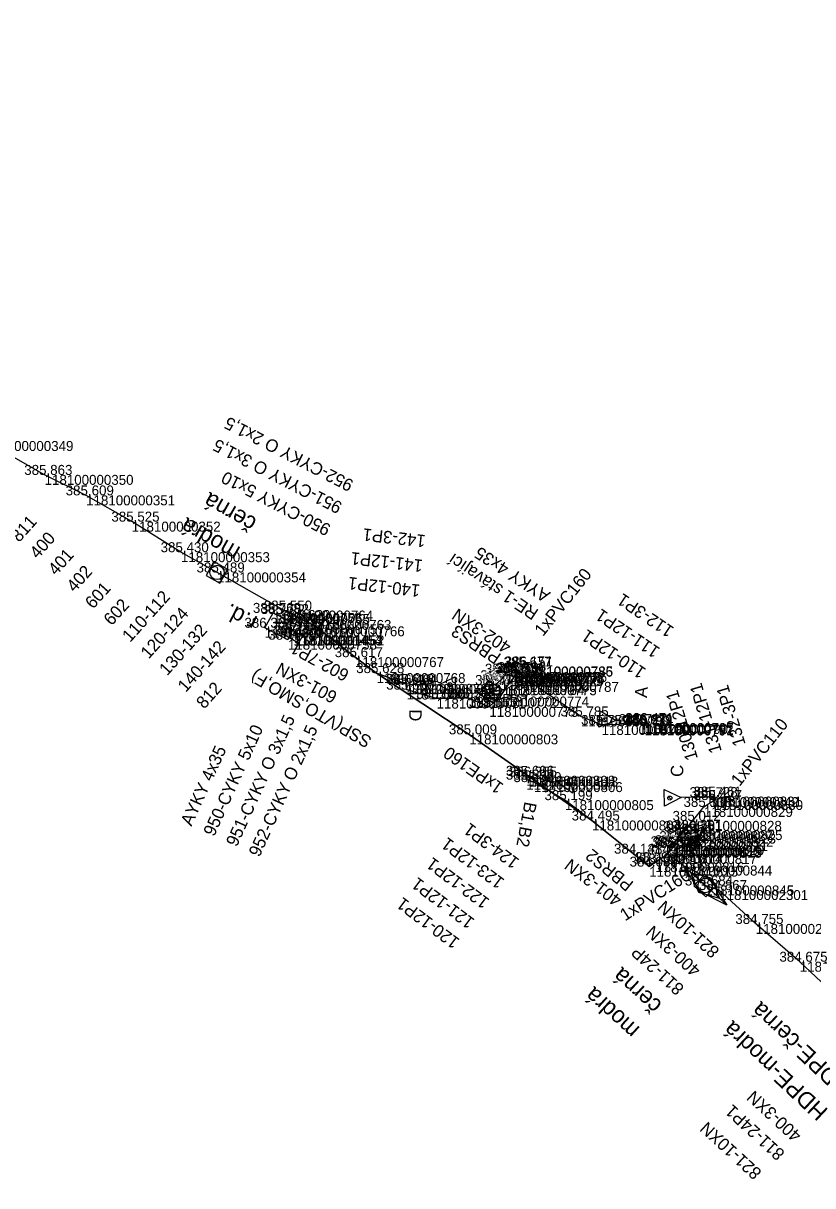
# Model space of a CAD drawing. Extents: x -724084 to -720954, y -948423 to -945131.
# Drawn here: x -721591.6 to -721496.5, y -947941.8 to -947801.8 of the extents above; entities that cross this region are included whole.
import ezdxf

# ---------------------------------------------------------------- set-up
doc = ezdxf.new("R2010")
doc.units = 0
for name, color, linetype in [('Vrstva 25', 7, 'Continuous'), ('Vrstva 26', 7, 'Continuous'), ('Vrstva 27', 7, 'Continuous'), ('Vrstva 28', 7, 'Continuous'), ('Vrstva 3', 7, 'Continuous'), ('Vrstva 31', 7, 'Continuous'), ('Vrstva 33', 7, 'Continuous'), ('Vrstva 35', 7, 'Continuous'), ('Vrstva 4', 7, 'Continuous'), ('Vrstva 60', 7, 'Continuous'), ('Vrstva 61', 7, 'Continuous')]:
    doc.layers.add(name, color=color, linetype=linetype)

msp = doc.modelspace()

# ---------------------------------------------------------------- linework, layer by layer
at = {"layer": 'Vrstva 25'}
for points in [[(-721557.94, -947875.57), (-721558.44, -947876.44), (-721560.17, -947875.43), (-721559.67, -947874.57), (-721557.94, -947875.57)], [(-721530.42, -947879.79), (-721530.98, -947880.62), (-721532.64, -947879.51), (-721532.08, -947878.68), (-721530.42, -947879.79)]]:
    msp.add_lwpolyline(points, dxfattribs=at)
at = {"layer": 'Vrstva 26'}
for points in [[(-721557.95, -947873.64), (-721560.15, -947872.51), (-721560.53, -947872.92)], [(-721559.05, -947875.5), (-721558.98, -947875.53), (-721558.79, -947875.5), (-721557.95, -947873.64)], [(-721531.25, -947879.24), (-721531.28, -947879.28), (-721531.98, -947879.92), (-721533.23, -947881.51), (-721534.14, -947882.86), (-721535.45, -947884.11), (-721538, -947883.03), (-721541.8, -947883.11), (-721545.42, -947882.03), (-721545.45, -947881.34), (-721549.03, -947880.04), (-721551.62, -947878.12), (-721556.35, -947874.41), (-721557.95, -947873.64)]]:
    msp.add_lwpolyline(points, dxfattribs=at)
at = {"layer": 'Vrstva 27'}
for p, q in [((-721532.25, -947880.11), (-721532.33, -947880.06)), ((-721513.24, -947901.02), (-721513.32, -947900.96))]:
    msp.add_line(p, q, dxfattribs=at)
for points in [[(-721559.7, -947876.02), (-721562.49, -947874.58), (-721561.47, -947872.79), (-721558.78, -947874.16), (-721559.7, -947876.02)], [(-721532.29, -947880.08), (-721532.46, -947880.37), (-721532.77, -947880.42), (-721533.52, -947880.12), (-721534.07, -947880.9), (-721534.72, -947881.47)], [(-721513.28, -947900.99), (-721513.06, -947900.77), (-721512.62, -947900.28), (-721511.95, -947899.76), (-721511.64, -947899.37), (-721510.86, -947898.95)]]:
    msp.add_lwpolyline(points, dxfattribs=at)
for centre in [(-721532.29, -947880.08), (-721513.28, -947900.99)]:
    msp.add_circle(centre, 0.5, dxfattribs=at)
at = {"layer": 'Vrstva 28'}
for p, q in [((-721506.87, -947907.96), (-721512.03, -947903.27)), ((-721510.23, -947906.48), (-721511.17, -947904.05)), ((-721511.17, -947904.05), (-721508.67, -947904.75)), ((-721508.67, -947904.75), (-721507.73, -947907.18)), ((-721507.73, -947907.18), (-721510.23, -947906.48))]:
    msp.add_line(p, q, dxfattribs=at)
for points in [[(-721560.15, -947872.51), (-721568.24, -947867.92), (-721572.58, -947865.48), (-721578.51, -947861.8), (-721584, -947858.64), (-721589, -947856.17), (-721596.24, -947852.09), (-721602.86, -947848.59), (-721606.08, -947846.62), (-721610.38, -947844.41), (-721614.4, -947841.85), (-721618.55, -947839.33), (-721627.06, -947834.09), (-721634.1, -947829.95), (-721642.58, -947825.32), (-721647.14, -947823.7), (-721653.32, -947819.98), (-721655.37, -947818.3), (-721658.37, -947816.2), (-721665.02, -947812.16), (-721667.86, -947809.89), (-721672.1, -947807.72), (-721674.53, -947807.12), (-721683.46, -947801.78)], [(-721560.53, -947872.92), (-721560.15, -947872.51)], [(-721560.15, -947872.51), (-721557.95, -947873.64)], [(-721559.05, -947875.5), (-721558.98, -947875.53), (-721558.79, -947875.5), (-721557.95, -947873.64)], [(-721557.95, -947873.64), (-721556.35, -947874.41), (-721551.62, -947878.12), (-721549.03, -947880.04)], [(-721549.03, -947880.04), (-721537.87, -947887.42), (-721523.09, -947897.79)], [(-721549.03, -947880.04), (-721545.45, -947881.34)], [(-721545.45, -947881.34), (-721545.42, -947882.03), (-721541.8, -947883.11), (-721538, -947883.03), (-721535.45, -947884.11), (-721534.14, -947882.86), (-721533.23, -947881.51), (-721531.98, -947879.92)], [(-721531.98, -947879.92), (-721532.21, -947879.99), (-721532.29, -947880.08)], [(-721516.72, -947886.05), (-721516.74, -947886.22), (-721516.75, -947886.35), (-721517.42, -947886.18), (-721521.94, -947886.29), (-721524.42, -947885.26), (-721530.56, -947881.1), (-721531.98, -947879.92)], [(-721545.05, -947881.39), (-721545.45, -947881.34)], [(-721523.09, -947897.79), (-721526.36, -947895.34), (-721530.09, -947893.17), (-721531, -947892.87), (-721531.01, -947892.41), (-721530.64, -947892.51)], [(-721513.94, -947901.83), (-721513.57, -947900.89), (-721512.03, -947899.08), (-721510.94, -947897.84), (-721509.61, -947896.16), (-721508.39, -947895.33), (-721508.52, -947894.91), (-721508.88, -947894.98)], [(-721523.09, -947897.79), (-721518.09, -947901.79), (-721516.2, -947903.35), (-721515.45, -947902.81), (-721513.94, -947901.83)], [(-721513.94, -947901.83), (-721513.36, -947901.08), (-721513.28, -947900.99)], [(-721448.03, -947967.83), (-721449.45, -947966.46), (-721453.79, -947960.88), (-721457.95, -947955.95), (-721463.02, -947949.85), (-721466.62, -947945.71), (-721471.84, -947940.17), (-721476.02, -947936), (-721481.4, -947930.25), (-721486.36, -947925.65), (-721492.33, -947920.18), (-721498.07, -947914.8), (-721503.37, -947910.25), (-721507.77, -947906.17), (-721509.45, -947905.62), (-721512.09, -947903.22), (-721513.94, -947901.83)]]:
    msp.add_lwpolyline(points, dxfattribs=at)
at = {"layer": 'Vrstva 3'}
for p, q in [((-721536.07, -947881.69), (-721534.77, -947881.43)), ((-721535.77, -947881.25), (-721535.21, -947881.14)), ((-721536.66, -947882.57), (-721533.89, -947882.03)), ((-721536.37, -947882.13), (-721534.33, -947881.73)), ((-721536.22, -947882.86), (-721534.18, -947882.47)), ((-721535.78, -947883.16), (-721534.48, -947882.91)), ((-721535.34, -947883.46), (-721534.78, -947883.35)), ((-721512.89, -947899.87), (-721510.08, -947899.58)), ((-721512.56, -947899.46), (-721510.49, -947899.25)), ((-721512.22, -947899.04), (-721510.9, -947898.91)), ((-721511.89, -947898.63), (-721511.31, -947898.57)), ((-721512.48, -947900.2), (-721510.42, -947899.99)), ((-721512.07, -947900.54), (-721510.75, -947900.4)), ((-721511.66, -947900.87), (-721511.09, -947900.81))]:
    msp.add_line(p, q, dxfattribs=at)
for points in [[(-721535.55, -947880.91), (-721533.89, -947882.03), (-721535, -947883.68), (-721536.66, -947882.57)], [(-721511.63, -947898.32), (-721510.08, -947899.58), (-721511.34, -947901.13), (-721512.89, -947899.87)]]:
    msp.add_lwpolyline(points, close=True, dxfattribs=at)
at = {"layer": 'Vrstva 31'}
for points in [[(-721560.15, -947872.51), (-721568.24, -947867.92), (-721572.58, -947865.48), (-721578.51, -947861.8), (-721584, -947858.64), (-721589, -947856.17), (-721596.24, -947852.09), (-721602.86, -947848.59), (-721606.08, -947846.62), (-721610.38, -947844.41), (-721614.4, -947841.85), (-721618.55, -947839.33), (-721627.06, -947834.09), (-721634.1, -947829.95), (-721642.58, -947825.32), (-721647.14, -947823.7), (-721653.32, -947819.98), (-721655.37, -947818.3), (-721658.37, -947816.2), (-721665.02, -947812.16), (-721667.86, -947809.89), (-721672.1, -947807.72), (-721674.53, -947807.12), (-721683.46, -947801.78)], [(-721560.15, -947872.51), (-721560.53, -947872.92)], [(-721557.95, -947873.64), (-721560.15, -947872.51)], [(-721549.03, -947880.04), (-721551.62, -947878.12), (-721556.35, -947874.41), (-721557.95, -947873.64)], [(-721523.09, -947897.79), (-721537.87, -947887.42), (-721549.03, -947880.04)], [(-721513.94, -947901.83), (-721515.45, -947902.81), (-721516.2, -947903.35), (-721518.09, -947901.79), (-721523.09, -947897.79)], [(-721448.03, -947967.83), (-721449.45, -947966.46), (-721453.79, -947960.88), (-721457.95, -947955.95), (-721463.02, -947949.85), (-721466.62, -947945.71), (-721471.84, -947940.17), (-721476.02, -947936), (-721481.4, -947930.25), (-721486.36, -947925.65), (-721492.33, -947920.18), (-721498.07, -947914.8), (-721503.37, -947910.25), (-721507.77, -947906.17), (-721509.45, -947905.62), (-721512.09, -947903.22), (-721513.94, -947901.83)], [(-721506.86, -947907.97), (-721510.12, -947906.36), (-721512.04, -947903.26), (-721508.78, -947904.88), (-721506.86, -947907.97)]]:
    msp.add_lwpolyline(points, dxfattribs=at)
at = {"layer": 'Vrstva 33'}
msp.add_lwpolyline([(-721492.33, -947920.18), (-721498.07, -947914.8), (-721503.37, -947910.25), (-721507.77, -947906.17), (-721509.45, -947905.62), (-721512.09, -947903.22), (-721513.94, -947901.83), (-721515.45, -947902.81), (-721516.2, -947903.35), (-721518.09, -947901.79), (-721523.09, -947897.79), (-721537.87, -947887.42), (-721549.03, -947880.04), (-721551.62, -947878.12), (-721556.35, -947874.41), (-721557.95, -947873.64), (-721560.15, -947872.51), (-721568.24, -947867.92), (-721572.58, -947865.48), (-721578.51, -947861.8), (-721584, -947858.64), (-721589, -947856.17), (-721596.24, -947852.09)], dxfattribs=at)
for points in [[(-721566.94, -947867.56), (-721568.61, -947866.61), (-721569.55, -947868.28), (-721567.88, -947869.23)], [(-721508.09, -947905.55), (-721509.52, -947904.26), (-721510.81, -947905.68), (-721509.38, -947906.97)]]:
    msp.add_lwpolyline(points, close=True, dxfattribs=at)
for centre in [(-721568.24, -947867.92), (-721509.45, -947905.62)]:
    msp.add_circle(centre, 0.864, dxfattribs=at)
at = {"layer": 'Vrstva 35'}
for points in [[(-721523.09, -947897.79), (-721537.87, -947887.42), (-721549.03, -947880.04)], [(-721535.45, -947884.11), (-721534.14, -947882.86), (-721533.23, -947881.51), (-721531.98, -947879.92)], [(-721513.57, -947900.89), (-721512.03, -947899.08), (-721510.94, -947897.84), (-721509.61, -947896.16), (-721508.39, -947895.33), (-721508.52, -947894.91), (-721508.88, -947894.98)], [(-721516.2, -947903.35), (-721515.45, -947902.81), (-721513.94, -947901.83)]]:
    msp.add_lwpolyline(points, dxfattribs=at)
at = {"layer": 'Vrstva 4'}
for p, q in [((-721545.03, -947880.61), (-721545.06, -947882.16)), ((-721540.37, -947881.25), (-721540.04, -947881.6)), ((-721521.39, -947885.86), (-721521.7, -947885.49)), ((-721516.78, -947886.82), (-721516.65, -947885.27)), ((-721530.5, -947891.75), (-721530.79, -947893.28)), ((-721526.02, -947893.18), (-721525.74, -947893.58)), ((-721508.87, -947895.76), (-721508.89, -947894.2)), ((-721513.55, -947895.26), (-721513.9, -947894.92))]:
    msp.add_line(p, q, dxfattribs=at)
for points in [[(-721545.05, -947881.39), (-721541.57, -947881.44), (-721539.55, -947880.48), (-721539.57, -947882.48), (-721541.57, -947881.44)], [(-721516.72, -947886.05), (-721520.18, -947885.76), (-721522.26, -947886.57), (-721522.1, -947884.58), (-721520.18, -947885.76)], [(-721530.64, -947892.51), (-721527.23, -947893.16), (-721525.07, -947892.56), (-721525.44, -947894.52), (-721527.23, -947893.16)], [(-721508.88, -947894.98), (-721512.36, -947895.04), (-721514.35, -947896.06), (-721514.39, -947894.06), (-721512.36, -947895.04)]]:
    msp.add_lwpolyline(points, dxfattribs=at)
for centre in [(-721540.21, -947881.43), (-721521.54, -947885.67), (-721525.88, -947893.38), (-721513.72, -947895.09)]:
    msp.add_circle(centre, 0.248, dxfattribs=at)
at = {"layer": 'Vrstva 60'}
for p, q in [((-721589, -947856.17), (-721589, -947856.17)), ((-721584, -947858.64), (-721584, -947858.64)), ((-721578.51, -947861.8), (-721578.51, -947861.8)), ((-721572.58, -947865.48), (-721572.58, -947865.48)), ((-721568.24, -947867.92), (-721568.24, -947867.92)), ((-721561.47, -947872.79), (-721561.47, -947872.79)), ((-721560.53, -947872.92), (-721560.53, -947872.92)), ((-721560.15, -947872.51), (-721560.15, -947872.51)), ((-721562.49, -947874.58), (-721562.49, -947874.58)), ((-721558.78, -947874.16), (-721558.78, -947874.16)), ((-721557.95, -947873.64), (-721557.95, -947873.64)), ((-721556.35, -947874.41), (-721556.35, -947874.41)), ((-721559.7, -947876.02), (-721559.7, -947876.02)), ((-721559.05, -947875.5), (-721559.05, -947875.5)), ((-721558.98, -947875.53), (-721558.98, -947875.53)), ((-721558.79, -947875.5), (-721558.79, -947875.5)), ((-721551.62, -947878.12), (-721551.62, -947878.12)), ((-721549.03, -947880.04), (-721549.03, -947880.04)), ((-721533.52, -947880.12), (-721533.52, -947880.12)), ((-721532.29, -947880.08), (-721532.29, -947880.08)), ((-721532.21, -947879.99), (-721532.21, -947879.99)), ((-721531.98, -947879.92), (-721531.98, -947879.92)), ((-721531.28, -947879.28), (-721531.28, -947879.28)), ((-721531.25, -947879.24), (-721531.25, -947879.24)), ((-721545.45, -947881.34), (-721545.45, -947881.34)), ((-721545.05, -947881.39), (-721545.05, -947881.39)), ((-721534.72, -947881.47), (-721534.72, -947881.47)), ((-721534.07, -947880.9), (-721534.07, -947880.9)), ((-721533.23, -947881.51), (-721533.23, -947881.51)), ((-721532.77, -947880.42), (-721532.77, -947880.42)), ((-721532.46, -947880.37), (-721532.46, -947880.37)), ((-721530.56, -947881.1), (-721530.56, -947881.1)), ((-721545.42, -947882.03), (-721545.42, -947882.03)), ((-721538, -947883.03), (-721538, -947883.03)), ((-721534.14, -947882.86), (-721534.14, -947882.86)), ((-721541.8, -947883.11), (-721541.8, -947883.11)), ((-721535.45, -947884.11), (-721535.45, -947884.11)), ((-721524.42, -947885.26), (-721524.42, -947885.26)), ((-721521.94, -947886.29), (-721521.94, -947886.29)), ((-721517.42, -947886.18), (-721517.42, -947886.18)), ((-721516.75, -947886.35), (-721516.75, -947886.35)), ((-721516.74, -947886.22), (-721516.74, -947886.22)), ((-721516.72, -947886.05), (-721516.72, -947886.05)), ((-721537.87, -947887.42), (-721537.87, -947887.42)), ((-721531.01, -947892.41), (-721531.01, -947892.41)), ((-721531, -947892.87), (-721531, -947892.87)), ((-721530.64, -947892.51), (-721530.64, -947892.51)), ((-721530.09, -947893.17), (-721530.09, -947893.17)), ((-721526.36, -947895.34), (-721526.36, -947895.34)), ((-721508.88, -947894.98), (-721508.88, -947894.98)), ((-721508.52, -947894.91), (-721508.52, -947894.91)), ((-721508.39, -947895.33), (-721508.39, -947895.33)), ((-721509.61, -947896.16), (-721509.61, -947896.16)), ((-721523.09, -947897.79), (-721523.09, -947897.79)), ((-721510.94, -947897.84), (-721510.94, -947897.84)), ((-721512.03, -947899.08), (-721512.03, -947899.08)), ((-721511.95, -947899.76), (-721511.95, -947899.76)), ((-721511.64, -947899.37), (-721511.64, -947899.37)), ((-721510.86, -947898.95), (-721510.86, -947898.95)), ((-721513.57, -947900.89), (-721513.57, -947900.89)), ((-721513.36, -947901.08), (-721513.36, -947901.08)), ((-721513.28, -947900.99), (-721513.28, -947900.99)), ((-721513.06, -947900.77), (-721513.06, -947900.77)), ((-721512.62, -947900.28), (-721512.62, -947900.28)), ((-721518.09, -947901.79), (-721518.09, -947901.79)), ((-721513.94, -947901.83), (-721513.94, -947901.83)), ((-721516.2, -947903.35), (-721516.2, -947903.35)), ((-721515.45, -947902.81), (-721515.45, -947902.81)), ((-721512.09, -947903.22), (-721512.09, -947903.22)), ((-721509.45, -947905.62), (-721509.45, -947905.62)), ((-721507.77, -947906.17), (-721507.77, -947906.17)), ((-721503.37, -947910.25), (-721503.37, -947910.25)), ((-721498.07, -947914.8), (-721498.07, -947914.8))]:
    msp.add_line(p, q, dxfattribs=at)

# ---------------------------------------------------------------- texts
at = {"layer": 'Vrstva 25'}
for s, rotation, p in [('RE-1 stávající', 146.0312, (-721529.41, -947872.5)), ('SSP(VTO,SMO,F)', 149.863, (-721549.48, -947887.85))]:
    msp.add_text(s, height=1.5, rotation=rotation, dxfattribs=at).set_placement(p)
at = {"layer": 'Vrstva 26'}
for s, rotation, p in [('952-CYKY O 2x1,5', 152.7745, (-721551.67, -947856.92)), ('951-CYKY O 3x1,5', 152.7745, (-721553.04, -947859.59)), ('950-CYKY 5x10', 152.7745, (-721554.41, -947862.26)), ('AYKY 4x35', 146.7311, (-721528, -947870.37)), ('951-CYKY O 3x1,5', 65.5491, (-721565.86, -947901.04)), ('950-CYKY 5x10', 65.5491, (-721568.59, -947899.8)), ('952-CYKY O 2x1,5', 65.5491, (-721563.13, -947902.28)), ('AYKY 4x35', 65.5491, (-721571.32, -947898.56))]:
    msp.add_text(s, height=1.5, rotation=rotation, dxfattribs=at).set_placement(p)
at = {"layer": 'Vrstva 27'}
for s, height, rotation, p in [('r.d.', 2, 152.7161, (-721563.22, -947873.33)), ('PBRS3', 1.5, 146.0312, (-721533.91, -947877.83)), ('PBRS2', 1.5, 140.8018, (-721517.97, -947905.28))]:
    msp.add_text(s, height=height, rotation=rotation, dxfattribs=at).set_placement(p)
at = {"layer": 'Vrstva 28'}
for s, rotation, p in [('811', 47.9898, (-721592.07, -947864.37)), ('400', 47.9898, (-721589.84, -947866.37)), ('142-3P1', 173.7071, (-721543.06, -947863.43)), ('401', 47.9898, (-721587.62, -947868.38)), ('141-12P1', 173.7071, (-721543.39, -947866.41)), ('402', 47.9898, (-721585.39, -947870.39)), ('140-12P1', 173.7071, (-721543.72, -947869.4)), ('601', 47.9898, (-721583.16, -947872.4)), ('110-112', 47.9898, (-721578.7, -947876.41)), ('112-3P1', 145.8663, (-721513.1, -947874.62)), ('602', 47.9898, (-721580.93, -947874.41)), ('120-124', 47.9898, (-721576.47, -947878.42)), ('402-3XN', 146.3997, (-721532.68, -947876.55)), ('111-12P1', 145.8663, (-721514.78, -947877.1)), ('130-132', 47.9898, (-721574.24, -947880.43)), ('110-12P1', 145.8663, (-721516.47, -947879.59)), ('140-142', 47.9898, (-721572.01, -947882.44)), ('602-7P1', 151.5869, (-721552.2, -947879.81)), ('601-3XN', 151.5869, (-721553.63, -947882.45)), ('812', 47.9898, (-721569.78, -947884.44)), ('131-12P1', 106.6005, (-721507.44, -947889.45)), ('132-3P1', 106.6005, (-721504.57, -947888.6)), ('130-12P1', 106.6005, (-721510.32, -947890.31)), ('124-3P1', 143.2564, (-721531.73, -947902.54)), ('123-12P1', 143.2564, (-721533.52, -947904.95)), ('122-12P1', 143.2564, (-721535.32, -947907.35)), ('401-3XN', 142.7849, (-721519.34, -947907.09)), ('121-12P1', 143.2564, (-721537.11, -947909.76)), ('120-12P1', 143.2564, (-721538.91, -947912.16)), ('400-3XN', 137.7545, (-721509.87, -947915.65)), ('811-24P', 137.7545, (-721511.89, -947917.87)), ('400-3XN', 137.447, (-721497.74, -947935.56)), ('811-24P1', 137.447, (-721499.77, -947937.77))]:
    msp.add_text(s, height=1.5, rotation=rotation, dxfattribs=at).set_placement(p)
at = {"layer": 'Vrstva 31'}
for rotation, p in [(137.7545, (-721507.64, -947913.39)), (137.447, (-721502.56, -947940.07))]:
    msp.add_text('821-10XN', height=1.5, rotation=rotation, dxfattribs=at).set_placement(p)
at = {"layer": 'Vrstva 33'}
for s, rotation, p in [('černá', 150.4285, (-721563.31, -947861.49)), ('modrá', 150.4285, (-721565.29, -947864.97)), ('černá', 137.7545, (-721514.53, -947919.84)), ('modrá', 137.7545, (-721517.22, -947922.8)), ('HDPE-černá', 136.8772, (-721491.8, -947929.74)), ('HDPE-modrá', 136.8772, (-721494.54, -947932.66))]:
    msp.add_text(s, height=2, rotation=rotation, dxfattribs=at).set_placement(p)
at = {"layer": 'Vrstva 35'}
for s, rotation, p in [('1xPVC160', 51.663, (-721528.98, -947875.7)), ('1xPVC110', 51.7375, (-721505.32, -947893.77)), ('1xPE160', 144.9614, (-721533.62, -947893.48)), ('1xPVC160', 32.8958, (-721519.11, -947909.96))]:
    msp.add_text(s, height=1.5, rotation=rotation, dxfattribs=at).set_placement(p)
at = {"layer": 'Vrstva 4'}
for s, rotation, p in [('A', 85.2401, (-721516.47, -947883.06)), ('D', 269.2049, (-721545.09, -947884.39)), ('C', 91.0132, (-721512.08, -947892.53)), ('B1,B2', 259.4044, (-721531.2, -947895.46))]:
    msp.add_text(s, height=1.5, rotation=rotation, dxfattribs=at).set_placement(p)
at = {"layer": 'Vrstva 60'}
for s, p in [('118100000349', (-721596.24, -947853.29)), ('118100000350', (-721589, -947857.37)), ('118100000351', (-721584, -947859.84)), ('118100000352', (-721578.51, -947863)), ('118100000353', (-721572.58, -947866.68)), ('118100000354', (-721568.24, -947869.12)), ('118100000756', (-721561.47, -947873.99)), ('118100000765', (-721560.53, -947874.12)), ('118100000764', (-721560.15, -947873.71)), ('118100000760', (-721562.49, -947875.78)), ('118100000757', (-721558.78, -947875.36)), ('118100000763', (-721557.95, -947874.84)), ('118100000766', (-721556.35, -947875.61)), ('118100000758', (-721559.7, -947877.22)), ('118100001454', (-721559.05, -947876.7)), ('118100001453', (-721558.98, -947876.73)), ('118100001452', (-721558.79, -947876.7)), ('118100000767', (-721551.62, -947879.32)), ('118100000768', (-721549.03, -947881.24)), ('118100000781', (-721533.52, -947881.33)), ('118100000778', (-721532.29, -947881.28)), ('118100000777', (-721532.21, -947881.19)), ('118100000776', (-721531.98, -947881.12)), ('118100000786', (-721531.28, -947880.48)), ('118100000785', (-721531.25, -947880.44)), ('118100000769', (-721545.45, -947882.54)), ('118100000802', (-721545.05, -947882.59)), ('118100000784', (-721534.72, -947882.67)), ('118100000782', (-721534.07, -947882.1)), ('118100000775', (-721533.23, -947882.71)), ('118100000780', (-721532.77, -947881.62)), ('118100000779', (-721532.46, -947881.57)), ('118100000787', (-721530.56, -947882.3)), ('118100000770', (-721545.42, -947883.22)), ('118100000772', (-721538, -947884.23)), ('118100000774', (-721534.14, -947884.06)), ('118100000771', (-721541.8, -947884.31)), ('118100000773', (-721535.45, -947885.31)), ('118100000788', (-721524.42, -947886.46)), ('118100000789', (-721521.94, -947887.49)), ('118100000790', (-721517.42, -947887.38)), ('118100000791', (-721516.75, -947887.55)), ('118100000792', (-721516.74, -947887.42)), ('118100000797', (-721516.72, -947887.25)), ('118100000803', (-721537.87, -947888.62)), ('118100000808', (-721531.01, -947893.61)), ('118100000807', (-721531, -947894.07)), ('118100000813', (-721530.64, -947893.71)), ('118100000806', (-721530.09, -947894.37)), ('118100000805', (-721526.36, -947896.54)), ('118100000842', (-721508.88, -947896.18)), ('118100000831', (-721508.52, -947896.11)), ('118100000830', (-721508.39, -947896.53)), ('118100000829', (-721509.61, -947897.36)), ('118100000804', (-721523.09, -947898.99)), ('118100000828', (-721510.94, -947899.04)), ('118100000827', (-721512.03, -947900.28)), ('118100000822', (-721511.95, -947900.96)), ('118100000823', (-721511.64, -947900.57)), ('118100000825', (-721510.86, -947900.15)), ('118100000826', (-721513.57, -947902.09)), ('118100000818', (-721513.36, -947902.28)), ('118100000819', (-721513.28, -947902.19)), ('118100000820', (-721513.06, -947901.97)), ('118100000821', (-721512.62, -947901.48)), ('118100000814', (-721518.09, -947902.99)), ('118100000817', (-721513.94, -947903.03)), ('118100000815', (-721516.2, -947904.55)), ('118100000816', (-721515.45, -947904.01)), ('118100000844', (-721512.09, -947904.42)), ('118100000845', (-721509.45, -947906.82)), ('118100002301', (-721507.77, -947907.37)), ('118100002300', (-721503.37, -947911.45)), ('118100002299', (-721498.07, -947916))]:
    msp.add_text(s, height=1.2, dxfattribs=at).set_placement(p)
at = {"layer": 'Vrstva 61'}
for s, p in [('385.863', (-721591.45, -947856.17)), ('385.609', (-721586.46, -947858.64)), ('385.525', (-721580.96, -947861.8)), ('385.430', (-721575.03, -947865.48)), ('385.489', (-721570.7, -947867.92)), ('385.769', (-721563.92, -947872.79)), ('385.752', (-721562.97, -947872.92)), ('385.550', (-721562.6, -947872.51)), ('386.390', (-721561.23, -947874.16)), ('385.620', (-721560.4, -947873.64)), ('385.640', (-721558.81, -947874.41)), ('386.364', (-721564.94, -947874.58)), ('386.333', (-721561.5, -947875.5)), ('386.050', (-721561.43, -947875.53)), ('385.785', (-721561.24, -947875.5)), ('386.241', (-721562.06, -947876.02)), ('385.617', (-721554.07, -947878.12)), ('385.628', (-721551.48, -947880.04)), ('386.010', (-721534.74, -947880.08)), ('385.734', (-721534.66, -947879.99)), ('385.500', (-721534.43, -947879.92)), ('385.677', (-721533.73, -947879.28)), ('386.151', (-721533.6, -947879.24)), ('385.618', (-721547.9, -947881.34)), ('386.464', (-721547.5, -947881.39)), ('386.272', (-721537.16, -947881.47)), ('386.125', (-721536.53, -947880.9)), ('386.155', (-721535.98, -947880.12)), ('386.101', (-721535.13, -947880.42)), ('386.161', (-721534.82, -947880.37)), ('385.647', (-721533.01, -947881.1)), ('385.580', (-721547.87, -947882.03)), ('385.102', (-721536.59, -947882.86)), ('385.169', (-721535.69, -947881.51)), ('385.586', (-721544.25, -947883.11)), ('385.508', (-721540.46, -947883.03)), ('385.555', (-721537.91, -947884.11)), ('385.785', (-721526.88, -947885.26)), ('385.759', (-721524.4, -947886.29)), ('385.727', (-721519.87, -947886.18)), ('385.732', (-721519.2, -947886.35)), ('385.679', (-721519.2, -947886.22)), ('386.471', (-721519.07, -947886.05)), ('385.009', (-721540.32, -947887.42)), ('385.606', (-721533.46, -947892.41)), ('386.355', (-721533.1, -947892.51)), ('385.595', (-721533.46, -947892.87)), ('385.389', (-721532.55, -947893.17)), ('385.199', (-721528.81, -947895.34)), ('385.728', (-721511.34, -947894.98)), ('385.461', (-721510.87, -947894.91)), ('385.427', (-721510.84, -947895.33)), ('385.335', (-721512.07, -947896.16)), ('384.495', (-721525.54, -947897.79)), ('385.012', (-721513.39, -947897.84)), ('384.958', (-721514.48, -947899.08)), ('385.922', (-721514.09, -947899.37)), ('386.201', (-721513.21, -947898.95)), ('385.075', (-721516.03, -947900.89)), ('385.146', (-721515.81, -947901.08)), ('385.948', (-721515.73, -947900.99)), ('385.742', (-721515.51, -947900.77)), ('385.941', (-721514.98, -947900.28)), ('386.019', (-721514.41, -947899.76)), ('384.141', (-721520.44, -947901.79)), ('384.842', (-721516.39, -947901.83)), ('384.081', (-721518.56, -947903.35)), ('383.960', (-721517.9, -947902.81)), ('384.910', (-721514.54, -947903.22)), ('384.684', (-721511.9, -947905.62)), ('384.867', (-721510.22, -947906.17)), ('384.755', (-721505.83, -947910.25)), ('384.675', (-721500.52, -947914.8))]:
    msp.add_text(s, height=1.2, dxfattribs=at).set_placement(p)

doc.saveas('drawing.dxf')
